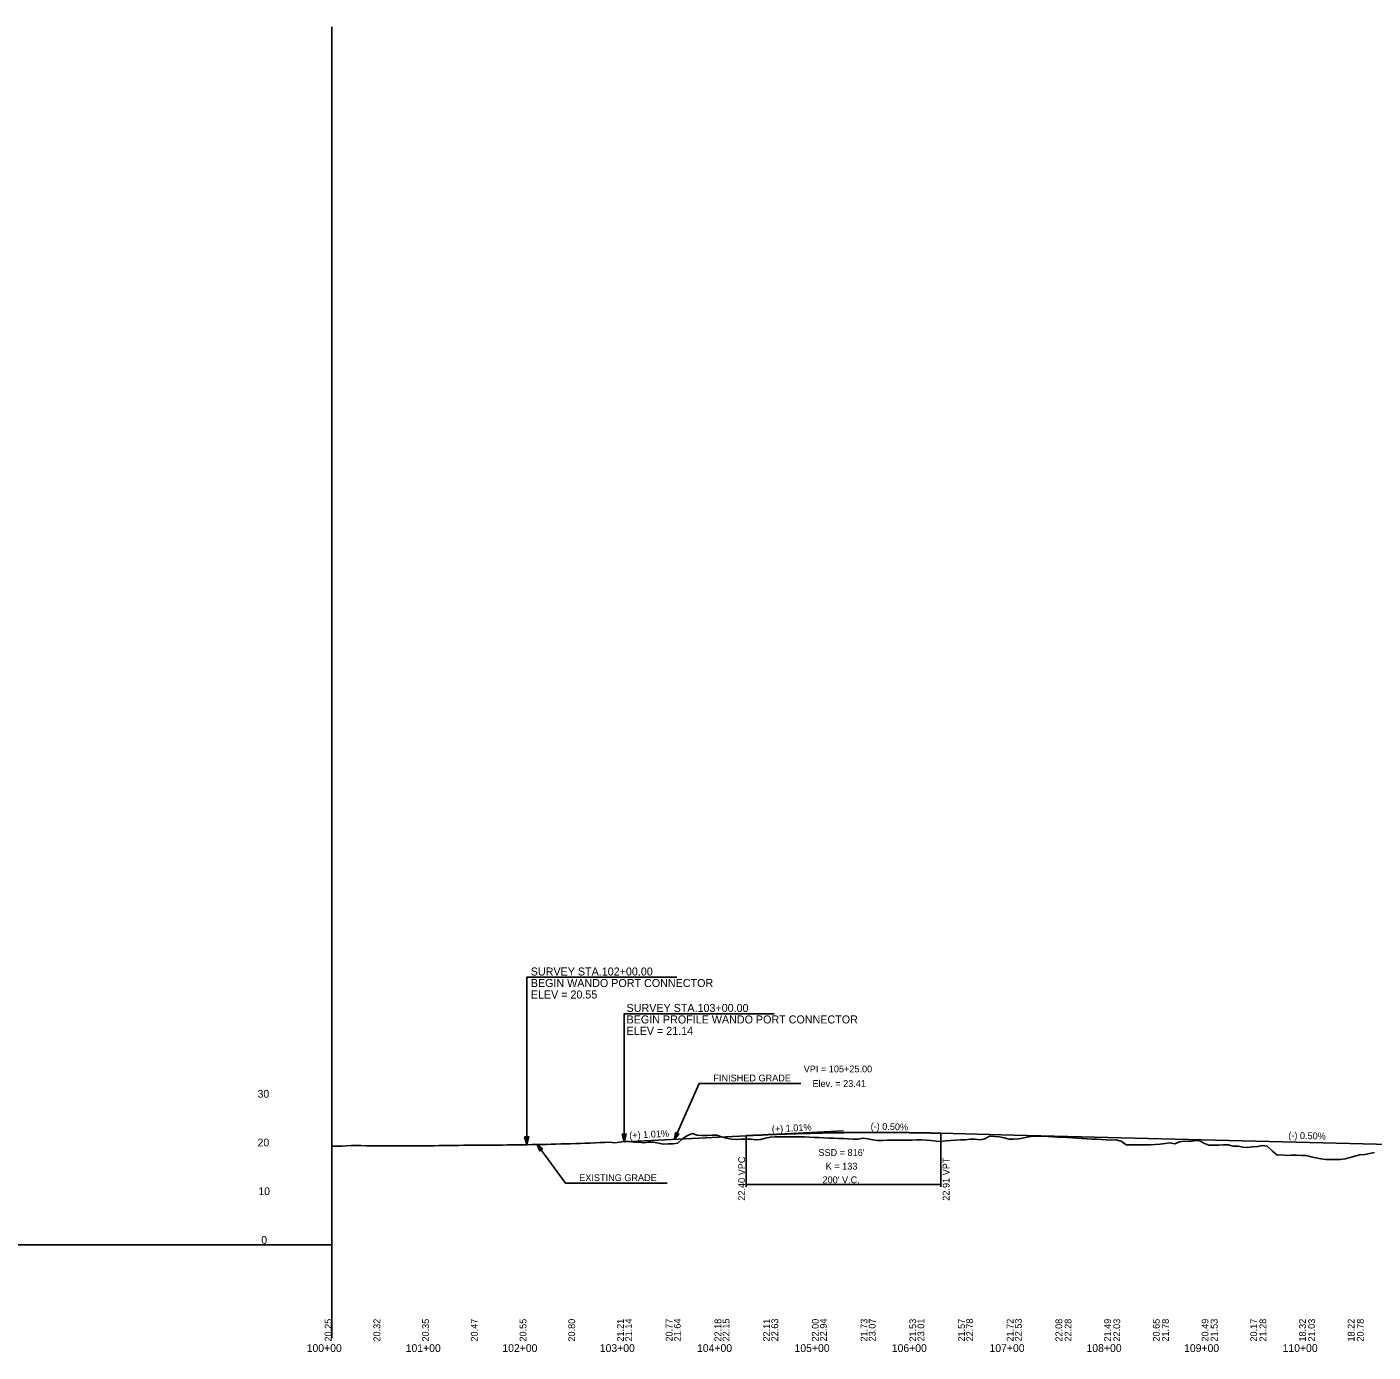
# Model space of a CAD drawing. Extents: x 2360994 to 2383826, y 330623 to 403123.
# Drawn here: x 2368513 to 2369894, y 336763 to 338123 of the extents above; entities that cross this region are included whole.
import ezdxf

# ---------------------------------------------------------------- set-up
doc = ezdxf.new("R2010")
doc.units = 0
for name, color, linetype in [('RD_DDB_ElevTX', 7, 'Continuous'), ('RD_DDB_GradeTX', 7, 'Continuous'), ('RD_DDB_Profile_EX', 7, 'Continuous'), ('RD_DDB_Profile_Lbl', 7, 'Continuous'), ('RD_DDB_Profile_PR', 7, 'Continuous'), ('RD_DDB_StaTX', 7, 'Continuous'), ('RD_DDB_StripGrade', 7, 'Continuous'), ('RD_DDB_VCLbl', 7, 'Continuous'), ('RD_GPK_Profile_Cell', 7, 'Continuous'), ('RD_SHT_Misc1', 7, 'Continuous'), ('RD_TX_Profile', 7, 'Continuous')]:
    doc.layers.add(name, color=color, linetype=linetype)

msp = doc.modelspace()

# ---------------------------------------------------------------- linework, layer by layer
at = {"layer": 'RD_DDB_GradeTX'}
for p, q in [((2369250.6, 336984.9), (2369350.6, 336989.9)), ((2369430.5, 336987.9), (2369450.6, 336987.4))]:
    msp.add_line(p, q, dxfattribs=at)
at = {"layer": 'RD_DDB_Profile_EX'}
for points in [[(2368825.6, 336974.1), (2368830.6, 336974.1), (2368835.6, 336974.3), (2368840.6, 336974.6), (2368845.6, 336974.7), (2368850.6, 336974.7), (2368855.6, 336974.7), (2368860.6, 336974.6), (2368865.6, 336974.5), (2368870.6, 336974.5), (2368875.6, 336974.5), (2368880.6, 336974.5), (2368885.6, 336974.5), (2368890.6, 336974.5), (2368895.6, 336974.5), (2368900.6, 336974.5), (2368905.6, 336974.5), (2368910.6, 336974.5), (2368915.6, 336974.6), (2368920.6, 336974.6), (2368925.6, 336974.6), (2368930.6, 336974.6), (2368935.6, 336974.7), (2368940.6, 336974.8), (2368945.6, 336974.9), (2368950.6, 336975), (2368955.6, 336975), (2368960.6, 336975.1), (2368965.6, 336975.1), (2368970.6, 336975.2), (2368975.6, 336975.2), (2368980.6, 336975.3), (2368985.6, 336975.3), (2368990.6, 336975.3), (2368995.6, 336975.3), (2369000.6, 336975.3), (2369005.6, 336975.4), (2369010.6, 336975.5), (2369015.6, 336975.5), (2369020.6, 336975.6), (2369025.6, 336975.6), (2369030.6, 336975.7), (2369035.6, 336975.8), (2369040.6, 336975.9), (2369045.6, 336976), (2369050.6, 336976.1), (2369055.6, 336976.2), (2369060.6, 336976.4), (2369065.6, 336976.5), (2369070.6, 336976.7), (2369075.6, 336976.9), (2369080.6, 336977), (2369085.6, 336977.2), (2369090.6, 336977.4), (2369095.6, 336977.7), (2369100.6, 336977.8), (2369105.6, 336978), (2369110.6, 336978.1), (2369115.6, 336977.6), (2369120.6, 336978.3), (2369125.6, 336978.9), (2369130.6, 336979), (2369135.6, 336978.3), (2369140.6, 336978.1), (2369145.6, 336977.7), (2369150.6, 336978.1), (2369155.6, 336978.1), (2369160.6, 336977.4), (2369165.6, 336976.3), (2369170.6, 336976.4), (2369175.6, 336976.7), (2369180.6, 336977.1), (2369185.6, 336982.1), (2369190.6, 336985.1), (2369195.6, 336987), (2369200.6, 336985.4), (2369205.6, 336985.2), (2369210.6, 336985.2), (2369215.6, 336985.4), (2369220.6, 336985.4), (2369225.6, 336983.8), (2369230.6, 336982.2), (2369235.6, 336981.5), (2369240.6, 336981.1), (2369245.6, 336981.3), (2369250.6, 336981.4), (2369255.6, 336981.5), (2369260.6, 336980.6), (2369265.6, 336981.1), (2369270.6, 336982.4), (2369275.6, 336983.4), (2369280.6, 336983.9), (2369285.6, 336983.8), (2369290.6, 336983.7), (2369295.6, 336983.7), (2369300.6, 336983.7), (2369305.6, 336983.7), (2369310.6, 336983.7), (2369315.6, 336983.5), (2369320.6, 336983.2), (2369325.6, 336982.9)], [(2369325.6, 336982.9), (2369330.6, 336982.7), (2369335.6, 336982.5), (2369340.6, 336982.3), (2369345.6, 336982.1), (2369350.6, 336981.9), (2369355.6, 336981.7), (2369360.6, 336981.5), (2369365.6, 336981.3), (2369370.6, 336982.5), (2369375.6, 336981.6), (2369380.6, 336980.7), (2369385.6, 336980.1), (2369390.6, 336980.1), (2369395.6, 336980.4), (2369400.6, 336980.4), (2369405.6, 336980.4), (2369410.6, 336980.3), (2369415.6, 336980.2), (2369420.6, 336980.3), (2369425.6, 336980.5), (2369430.6, 336980.5), (2369435.6, 336980.3), (2369440.6, 336979.9), (2369445.6, 336979.4), (2369450.6, 336979.1), (2369455.6, 336979.7), (2369460.6, 336980.1), (2369465.6, 336980.4), (2369470.6, 336980.5), (2369475.6, 336980.8), (2369480.6, 336981.2), (2369485.6, 336981.2), (2369490.6, 336980.7), (2369495.6, 336981.7), (2369500.6, 336984.3), (2369505.6, 336984.2), (2369510.6, 336983.9), (2369515.6, 336982.7), (2369520.6, 336981.4), (2369525.6, 336981.5), (2369530.6, 336981.6), (2369535.6, 336982.6), (2369540.6, 336983.8), (2369545.6, 336984.3), (2369550.6, 336984.5), (2369555.6, 336984.3), (2369560.6, 336984), (2369565.6, 336983.8), (2369570.6, 336983.5), (2369575.6, 336983.3), (2369580.6, 336983), (2369585.6, 336982.7), (2369590.6, 336982.4), (2369595.6, 336982.1), (2369600.6, 336981.8), (2369605.6, 336981.5), (2369610.6, 336981.2), (2369615.6, 336980.9), (2369620.6, 336980.6), (2369625.6, 336980.3), (2369630.6, 336980.7), (2369635.6, 336979.2), (2369640.6, 336975.5), (2369645.6, 336975.5), (2369650.6, 336975.4), (2369655.6, 336975.4), (2369660.6, 336975.4), (2369665.6, 336975.4), (2369670.6, 336975.8), (2369675.6, 336976.1), (2369680.6, 336976.8), (2369685.6, 336977.7), (2369690.6, 336976.6), (2369695.6, 336978.5), (2369700.6, 336979.2), (2369705.6, 336978.9), (2369710.6, 336979.6), (2369715.6, 336979.9), (2369720.6, 336977.2), (2369725.6, 336975.3), (2369730.6, 336975.1), (2369735.6, 336975.1), (2369740.6, 336975.5), (2369745.6, 336975.4), (2369750.6, 336974), (2369755.6, 336974.1), (2369760.6, 336973), (2369765.6, 336972.9), (2369770.6, 336973.6), (2369775.6, 336973.7), (2369780.6, 336974.7), (2369785.6, 336974.3), (2369790.6, 336969.3), (2369795.6, 336965), (2369800.6, 336965.1), (2369805.6, 336964.7), (2369810.6, 336965), (2369815.6, 336964.9), (2369820.6, 336964.5), (2369825.6, 336964.5)], [(2369825.6, 336964.5), (2369830.6, 336963.3), (2369835.6, 336962.1), (2369840.6, 336961), (2369845.6, 336960.4), (2369850.6, 336960.4), (2369855.6, 336960.4), (2369860.6, 336960.3), (2369865.6, 336961), (2369870.6, 336962.5), (2369875.6, 336964), (2369880.6, 336965.2), (2369885.6, 336965.7), (2369890.6, 336966.5), (2369895.6, 336967.6)]]:
    msp.add_lwpolyline(points, dxfattribs=at)
at = {"layer": 'RD_DDB_Profile_PR'}
for p, q in [((2369450.6, 336987.4), (2369525.6, 336985.5)), ((2369525.6, 336985.5), (2370755.6, 336954.8)), ((2369125.6, 336978.6), (2369250.6, 336984.9))]:
    msp.add_line(p, q, dxfattribs=at)
msp.add_spline([(2369250.6, 336984.9), (2369254.6, 336985.1), (2369258.6, 336985.3), (2369262.6, 336985.5), (2369266.6, 336985.6), (2369270.6, 336985.8), (2369274.6, 336986), (2369278.6, 336986.1), (2369282.6, 336986.3), (2369286.6, 336986.4), (2369290.6, 336986.6), (2369294.6, 336986.7), (2369298.6, 336986.9), (2369302.6, 336987), (2369306.6, 336987.1), (2369310.6, 336987.2), (2369314.6, 336987.3), (2369318.6, 336987.4), (2369322.6, 336987.5), (2369326.6, 336987.6), (2369330.6, 336987.7), (2369334.6, 336987.8), (2369338.6, 336987.9), (2369342.6, 336987.9), (2369346.6, 336988), (2369350.6, 336988), (2369354.6, 336988.1), (2369358.6, 336988.1), (2369362.6, 336988.2), (2369366.6, 336988.2), (2369370.6, 336988.2), (2369374.6, 336988.2), (2369378.6, 336988.2), (2369382.6, 336988.2), (2369386.6, 336988.2), (2369390.6, 336988.2), (2369394.6, 336988.2), (2369398.6, 336988.2), (2369402.6, 336988.2), (2369406.6, 336988.1), (2369410.6, 336988.1), (2369414.6, 336988.1), (2369418.6, 336988), (2369422.6, 336988), (2369426.6, 336987.9), (2369430.6, 336987.8), (2369434.6, 336987.8), (2369438.6, 336987.7), (2369442.6, 336987.6), (2369446.6, 336987.5), (2369450.6, 336987.4)], degree=3, dxfattribs=at)
at = {"layer": 'RD_DDB_VCLbl'}
for p, q in [((2369450.6, 336932.4), (2369450.6, 336987.4)), ((2369250.6, 336932.4), (2369250.6, 336984.9)), ((2369250.6, 336934.9), (2369450.6, 336934.9))]:
    msp.add_line(p, q, dxfattribs=at)
at = {"layer": 'RD_GPK_Profile_Cell'}
msp.add_line((2368825.6, 338122.9), (2368825.6, 336777), dxfattribs=at)
at = {"layer": 'RD_SHT_Misc1'}
msp.add_line((2368825.6, 336872.9), (2364659.3, 336872.9), dxfattribs=at)
at = {"layer": 'RD_TX_Profile'}
for p, q in [((2369179.5, 337147.5), (2369040.5, 337147.5)), ((2369279.5, 337110.1), (2369140.5, 337110.1)), ((2369306.7, 337038.6), (2369212.1, 337038.6)), ((2369169.5, 336936.3), (2369074.4, 336936.3))]:
    msp.add_line(p, q, dxfattribs=at)
for points in [[(2369040.5, 337147.5), (2369025.6, 337147.5), (2369025.6, 336975.6)], [(2369140.5, 337110.1), (2369125.6, 337110.1), (2369125.6, 336978.6)], [(2369212.1, 337038.6), (2369202.4, 337038.6), (2369177.1, 336981.2)], [(2369074.4, 336936.3), (2369065.3, 336936.3), (2369036.4, 336975.8)]]:
    msp.add_lwpolyline(points, dxfattribs=at)
for points in [[(2369123.4, 336986.5), (2369125.6, 336978.6), (2369127.7, 336986.5)], [(2369178.2, 336988.1), (2369177.1, 336981.2), (2369181.5, 336986.6)], [(2369023.4, 336983.6), (2369025.6, 336975.6), (2369027.7, 336983.6)], [(2369041.8, 336971.5), (2369036.4, 336975.8), (2369038.9, 336969.3)]]:
    msp.add_lwpolyline(points, close=True, dxfattribs=at)

# ---------------------------------------------------------------- texts
at = {"layer": 'RD_DDB_ElevTX'}
for s, p in [('30', (2368749.3, 337023.9)), ('20', (2368749.3, 336973.9)), ('10', (2368750.1, 336923.9)), ('0', (2368753.1, 336873.9))]:
    msp.add_text(s, height=8, dxfattribs=at).set_placement(p)
at = {"layer": 'RD_DDB_GradeTX'}
for s, rotation, p in [('(+) 1.01%', 2.8836, (2369130.9, 336981.8)), ('(+) 1.01%', 2.8836, (2369277.2, 336988.2)), ('(-) 0.50%', 358.5679, (2369378.4, 336991.2)), ('(-) 0.50%', 358.5679, (2369807.1, 336981.9))]:
    msp.add_text(s, height=7, rotation=rotation, dxfattribs=at).set_placement(p)
at = {"layer": 'RD_DDB_Profile_Lbl'}
for s, p in [('VPI = 105+25.00', (2369309.8, 337049.9)), ('Elev. = 23.41', (2369318.8, 337034.9))]:
    msp.add_text(s, height=7, dxfattribs=at).set_placement(p)
at = {"layer": 'RD_DDB_StaTX'}
for s, p in [('100+00', (2368799.7, 336762.9)), ('101+00', (2368901.3, 336762.9)), ('102+00', (2369000.5, 336762.9)), ('103+00', (2369100.5, 336762.9)), ('104+00', (2369200.3, 336762.9)), ('105+00', (2369300.4, 336762.9)), ('106+00', (2369400.2, 336762.9)), ('107+00', (2369500.5, 336762.9)), ('108+00', (2369600.1, 336762.9)), ('109+00', (2369700.2, 336762.9)), ('110+00', (2369801.3, 336762.9))]:
    msp.add_text(s, height=8, dxfattribs=at).set_placement(p)
at = {"layer": 'RD_DDB_StripGrade'}
for s, p in [('22.40 VPC', (2369249.6, 336918.2)), ('22.91 VPT', (2369459.5, 336918.2)), ('20.25', (2368825.2, 336773.6)), ('20.32', (2368875.2, 336773.6)), ('20.35', (2368925.2, 336773.6)), ('20.47', (2368975.2, 336773.6)), ('20.55', (2369025.2, 336773.6)), ('20.80', (2369075.2, 336773.6)), ('21.21', (2369125.2, 336773.6)), ('21.14', (2369133.6, 336773.8)), ('20.77', (2369175.2, 336773.6)), ('21.64', (2369183.6, 336773.8)), ('22.18', (2369225.2, 336773.6)), ('22.15', (2369233.6, 336773.8)), ('22.11', (2369275.2, 336773.6)), ('22.63', (2369283.6, 336773.8)), ('22.00', (2369325.2, 336773.6)), ('22.94', (2369333.6, 336773.8)), ('21.73', (2369375.2, 336773.6)), ('23.07', (2369383.6, 336773.8)), ('21.53', (2369425.2, 336773.6)), ('23.01', (2369433.6, 336773.8)), ('21.57', (2369475.2, 336773.6)), ('22.78', (2369483.6, 336773.8)), ('21.72', (2369525.2, 336773.6)), ('22.53', (2369533.6, 336773.8)), ('22.08', (2369575.2, 336773.6)), ('22.28', (2369584.6, 336773.6)), ('21.49', (2369625.2, 336773.6)), ('22.03', (2369634.6, 336773.6)), ('20.65', (2369675.2, 336773.6)), ('21.78', (2369684.6, 336773.6)), ('20.49', (2369725.2, 336773.6)), ('21.53', (2369734.6, 336773.6)), ('20.17', (2369775.2, 336773.6)), ('21.28', (2369784.6, 336773.6)), ('18.32', (2369825.2, 336773.6)), ('21.03', (2369834.6, 336773.6)), ('18.22', (2369875.2, 336773.6)), ('20.78', (2369884.6, 336773.6))]:
    msp.add_text(s, height=7, rotation=90, dxfattribs=at).set_placement(p)
at = {"layer": 'RD_DDB_VCLbl'}
for s, p in [("SSD = 816'", (2369324.9, 336964.1)), ('K = 133', (2369332.4, 336950.1)), ("200' V.C.", (2369329.1, 336936.1))]:
    msp.add_text(s, height=7, dxfattribs=at).set_placement(p)
at = {"layer": 'RD_TX_Profile'}
for s, height, p in [('SURVEY STA.102+00.00', 8.235, (2369029.7, 337149.3)), ('BEGIN WANDO PORT CONNECTOR', 8.235, (2369029.7, 337137.5)), ('ELEV = 20.55', 8.235, (2369029.7, 337125.7)), ('SURVEY STA.103+00.00', 8.235, (2369128, 337111.9)), ('BEGIN PROFILE WANDO PORT CONNECTOR', 8.235, (2369128, 337100.1)), ('ELEV = 21.14', 8.235, (2369128, 337088.4)), ('FINISHED GRADE', 7, (2369217.1, 337040.6)), ('EXISTING GRADE', 7, (2369079.4, 336938.3))]:
    msp.add_text(s, height=height, dxfattribs=at).set_placement(p)

doc.saveas('drawing.dxf')
